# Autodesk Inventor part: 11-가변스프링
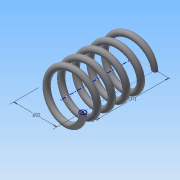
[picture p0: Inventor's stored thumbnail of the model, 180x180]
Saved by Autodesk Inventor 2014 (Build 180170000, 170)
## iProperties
Created: 2015-09
Part Number: 11-가변스프링
Material: Generic
Document SubType Name: Modeling
Designer: study
Density: 1 g/cm^3
Appearance: Default
Author: study
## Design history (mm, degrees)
sketch "스케치1"
  geometry: L1 (0, 0)-(11, 0); L2 (11, 0)-(11, 32.877); L3 (11, 32.877)-(0, 32.877); L4 (0, 32.877)-(0, 0); C1 r 1.5 at (11, 0); 1 further point
  constraints: 8 end point, 2 coincident, 2 parallel, 1 centre point, 1 horizontal, 1 perpendicular
  dimensions: "d0" = 22 diameter of L2 L4; "d1" = 32.8769 distance between parallel lines of L1 L3 (derived); "d2" = 3 diameter of C1
feature "코일1" sketch "스케치1" pitch "d3" = 10; turns "d5" = 5; dims "d4" = 32.8769 (= d1), "d6" = 0, angle "d7" = 90 deg, angle "d8" = 90 deg, "d9" = 0, "d10" = 0
node "작업 평면1"
sketch "스케치2"
  geometry: L1 (-12.5, 0)-(-9.5, 0) reference; 1 further point
  constraints: 1 horizontal alignment
extrude "돌출1" cut sketch "스케치2" stored distance "d12" = 10; taper "d13" = 0 deg
node "작업 평면2"
sketch "스케치3"
  geometry: L1 (-9.5, 0)-(-12.5, 0) reference; 1 further point
  constraints: 1 horizontal alignment
extrude "돌출2" cut sketch "스케치3" stored distance "d15" = 10; taper "d16" = 0 deg
node "솔리드1"
node "절단 모서리 투영1"
node "절단 모서리 투영2"
other parameters: "d11" = 0, "d14" = 32.8769 (= d1)
